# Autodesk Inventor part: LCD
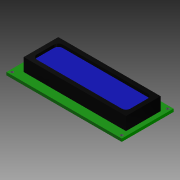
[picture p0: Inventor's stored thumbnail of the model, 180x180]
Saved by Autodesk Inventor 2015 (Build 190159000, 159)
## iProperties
Created: 2016-06
Part Number: LCD
Material: Genérico
Document SubType Name: Modeling
Designer: Diego
Density: 1 g/cm^3
Appearance: Valor por defecto
Author: Diego
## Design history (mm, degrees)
sketch "Boceto1"
  geometry: L1 (0, 0)-(80, 0); L2 (80, 0)-(80, 36); L3 (80, 36)-(0, 36); L4 (0, 36)-(0, 0)
  constraints: 8 end point, 2 parallel, 1 horizontal, 1 perpendicular
  dimensions: "d0" = 80 distance of L3.end L2.end; "d1" = 36 distance of L2.end L1.end
extrude "Extrusión1" new body sketch "Boceto1" distance "d2" = 2; taper "d3" = 0 deg
sketch "Boceto2"
  geometry: L1 (6, 30)-(77, 30); L2 (77, 30)-(77, 6); L3 (77, 6)-(6, 6); L4 (6, 6)-(6, 30); 1 further point
  constraints: 8 end point, 2 parallel, 1 horizontal, 1 perpendicular
  dimensions: "d10" = 71 distance of L2.end L3.end; "d11" = 24 distance of L1.end L2.end
extrude "Extrusión2" join sketch "Boceto2" distance "d12" = 9; taper "d13" = 0 deg
sketch "Boceto3"
  geometry: L1 (6, 30)-(6, 23); L2 (6, 30)-(6, 6) reference; L3 (6, 23)-(2, 23); L4 (6, 6)-(6, 13); L5 (6, 13)-(2, 13); L6 (2, 13)-(2, 23); L7 (6, 23)-(6, 13); 1 further point
  constraints: 12 end point, 2 parallel, 2 perpendicular, 2 point on line
  dimensions: "d14" = 7 distance of L1.start L1.end; "d15" = 4 distance of L1.end L3.end; "d16" = 7 distance of L2.end L4.end
extrude "Extrusión3" join sketch "Boceto3" distance "d17" = 5; taper "d18" = 0 deg
chamfer "Chaflán1" distance "d19" = 2; stored, may be unused: second distance "d20" = 2, angle "d21" = 45 deg
chamfer "Chaflán2" distance "d22" = 2; stored, may be unused: second distance "d23" = 2, angle "d24" = 45 deg
sketch "Boceto4"
  geometry: L1 (77, 30)-(6, 30) reference; L2 (6, 30)-(6, 6) reference; L3 (6, 6)-(77, 6) reference; L4 (77, 6)-(77, 30) reference; L5 (71, 9)-(12, 9); L6 (9, 12)-(9, 24); L7 (12, 27)-(71, 27); L8 (74, 24)-(74, 12); A1 r 3 centre (71, 12) between (71, 9) and (74, 12); A2 r 3 centre (71, 24) between (74, 24) and (71, 27); A3 r 3 centre (12, 24) between (12, 27) and (9, 24); A4 r 3 centre (12, 12) between (9, 12) and (12, 9); 1 further point
  constraints: 8 end point, 8 point on circle, 8 tangent, 4 centre point, 3 equal radius, 3 other
  dimensions: "d25" = 3 distance between parallel lines of L3 L5; "d26" = 3 radius of A1
extrude "Extrusión4" cut sketch "Boceto4" distance "d27" = 2; taper "d28" = 0 deg
sketch "Boceto5"
  geometry: L1 (0, 0)-(80, 0) reference; L2 (80, 0)-(80, 36) reference; L3 (80, 36)-(0, 36) reference; L4 (0, 36)-(0, 0) reference; L5 (6, 13)-(4, 13) reference; L6 (2, 15)-(4, 13) reference; L7 (2, 15)-(2, 21) reference; L8 (4, 23)-(2, 21) reference; L9 (4, 23)-(6, 23) reference; L10 (6, 23)-(6, 30) reference; L11 (6, 30)-(77, 30) reference; L12 (77, 30)-(77, 6) reference; L13 (77, 6)-(6, 6) reference; L14 (6, 6)-(6, 13) reference; L15 (78, 2)-(2, 2); L16 (2, 2)-(2, 34); L17 (2, 34)-(78, 34); L18 (78, 34)-(78, 2); 1 further point
  constraints: 8 end point, 3 other
  dimensions: "d29" = 2 distance between parallel lines of L1 L15
hole "Agujero1" sketch "Boceto5" at (78, 2), (78, 34), (2, 2), (2, 34) diameter "d30" = 2; stored, may be unused: countersink angle "d34" = 90 deg, drill point angle "d36" = 118 deg; dims "d31" = 6, "d32" = 4, "d33" = 2, "d35" = 8
sketch "Boceto6"
  geometry: L1 (-80, 0)-(-80, 36) reference; L2 (-80, 6)-(-36.384, 6); L3 (-77, 6)-(-6, 6) reference; L4 (-74.409, 6)-(-34.409, 6); L5 (-34.409, 6)-(-34.409, 8.5); L6 (-34.409, 8.5)-(-74.409, 8.5); L7 (-74.409, 8.5)-(-74.409, 6); 1 further point
  constraints: 10 end point, 3 point on line, 2 parallel, 1 horizontal, 1 perpendicular
  dimensions: "d37" = 40 distance of L6.end L5.end; "d38" = 2.5 distance of L5.end L4.end
extrude "Extrusión5" join sketch "Boceto6" distance "d39" = 2; taper "d40" = 0 deg
sketch "Boceto7" dims "d49" = 10
  geometry: L1 (-74.409, 6)-(-74.409, 8.5) reference; L2 (-34.409, 6)-(-34.409, 8.5) reference; L3 (-73.203, 7.25)-(-73.203, 6.5); L4 (-73.203, 6.5)-(-71.903, 6.5); L5 (-71.903, 6.5)-(-71.903, 7.8); L6 (-71.903, 7.8)-(-73.203, 7.8); L7 (-73.203, 7.8)-(-73.203, 6.5); L8 (-70.773, 7.25)-(-70.773, 6.5); L9 (-70.773, 6.5)-(-69.473, 6.5); L10 (-69.473, 6.5)-(-69.473, 7.8); L11 (-69.473, 7.8)-(-70.773, 7.8); L12 (-70.773, 7.8)-(-70.773, 6.5); L13 (-68.343, 7.25)-(-68.343, 6.5); L14 (-68.343, 6.5)-(-67.043, 6.5); L15 (-67.043, 6.5)-(-67.043, 7.8); L16 (-67.043, 7.8)-(-68.343, 7.8); L17 (-68.343, 7.8)-(-68.343, 6.5); L18 (-65.913, 7.25)-(-65.913, 6.5); L19 (-65.913, 6.5)-(-64.613, 6.5); L20 (-64.613, 6.5)-(-64.613, 7.8); L21 (-64.613, 7.8)-(-65.913, 7.8); L22 (-65.913, 7.8)-(-65.913, 6.5); L23 (-63.483, 7.25)-(-63.483, 6.5); L24 (-63.483, 6.5)-(-62.183, 6.5); L25 (-62.183, 6.5)-(-62.183, 7.8); L26 (-62.183, 7.8)-(-63.483, 7.8); L27 (-63.483, 7.8)-(-63.483, 6.5); L28 (-61.053, 7.25)-(-61.053, 6.5); L29 (-61.053, 6.5)-(-59.753, 6.5); L30 (-59.753, 6.5)-(-59.753, 7.8); L31 (-59.753, 7.8)-(-61.053, 7.8); L32 (-61.053, 7.8)-(-61.053, 6.5); L33 (-58.623, 7.25)-(-58.623, 6.5); L34 (-58.623, 6.5)-(-57.323, 6.5); L35 (-57.323, 6.5)-(-57.323, 7.8); L36 (-57.323, 7.8)-(-58.623, 7.8); L37 (-58.623, 7.8)-(-58.623, 6.5); L38 (-56.193, 7.25)-(-56.193, 6.5); L39 (-56.193, 6.5)-(-54.893, 6.5); L40 (-54.893, 6.5)-(-54.893, 7.8); L41 (-54.893, 7.8)-(-56.193, 7.8); L42 (-56.193, 7.8)-(-56.193, 6.5); L43 (-53.763, 7.25)-(-53.763, 6.5); L44 (-53.763, 6.5)-(-52.463, 6.5); L45 (-52.463, 6.5)-(-52.463, 7.8); L46 (-52.463, 7.8)-(-53.763, 7.8); L47 (-53.763, 7.8)-(-53.763, 6.5); L48 (-51.333, 7.25)-(-51.333, 6.5); L49 (-51.333, 6.5)-(-50.033, 6.5); L50 (-50.033, 6.5)-(-50.033, 7.8); L51 (-50.033, 7.8)-(-51.333, 7.8); L52 (-51.333, 7.8)-(-51.333, 6.5); L53 (-48.903, 7.25)-(-48.903, 6.5); L54 (-48.903, 6.5)-(-47.603, 6.5); L55 (-47.603, 6.5)-(-47.603, 7.8); L56 (-47.603, 7.8)-(-48.903, 7.8); L57 (-48.903, 7.8)-(-48.903, 6.5); L58 (-46.473, 7.25)-(-46.473, 6.5); L59 (-46.473, 6.5)-(-45.173, 6.5); L60 (-45.173, 6.5)-(-45.173, 7.8); L61 (-45.173, 7.8)-(-46.473, 7.8); L62 (-46.473, 7.8)-(-46.473, 6.5); L63 (-44.043, 7.25)-(-44.043, 6.5); L64 (-44.043, 6.5)-(-42.743, 6.5)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; 1 further point
  constraints: 160 end point, 2 horizontal, 2 parallel, 1 collinear, 1 perpendicular, 1 vertical, 149 other
  dimensions: "d41" = 0.75 distance of L3.start L3.end; "d42" = 1.3 distance of L6.end L5.end; "d43" = 1.3 distance of L5.end L4.end; "d46" = 2.43 distance of L3.start L8.start
extrude "Extrusión6" join sketch "Boceto7" distance "d51" = 4; taper "d52" = 0 deg
sketch "Boceto8" dims "d59" = 10
  geometry: L1 (-73.203, 6.5)-(-71.903, 6.5) reference; L2 (-71.903, 6.5)-(-71.903, 7.8) reference; L3 (-71.903, 7.8)-(-73.203, 7.8) reference; L4 (-73.203, 7.8)-(-73.203, 6.5) reference; L5 (-72.803, 7.4)-(-72.303, 7.4); L6 (-72.303, 7.4)-(-72.303, 6.9); L7 (-72.303, 6.9)-(-72.803, 6.9); L8 (-72.803, 6.9)-(-72.803, 7.4); L9 (-70.373, 6.9)-(-70.373, 7.4); L10 (-70.373, 7.4)-(-69.873, 7.4); L11 (-69.873, 6.9)-(-70.373, 6.9); L12 (-69.873, 7.4)-(-69.873, 6.9); L13 (-67.943, 6.9)-(-67.943, 7.4); L14 (-67.943, 7.4)-(-67.443, 7.4); L15 (-67.443, 6.9)-(-67.943, 6.9); L16 (-67.443, 7.4)-(-67.443, 6.9); L17 (-65.513, 6.9)-(-65.513, 7.4); L18 (-65.513, 7.4)-(-65.013, 7.4); L19 (-65.013, 6.9)-(-65.513, 6.9); L20 (-65.013, 7.4)-(-65.013, 6.9); L21 (-63.083, 6.9)-(-63.083, 7.4); L22 (-63.083, 7.4)-(-62.583, 7.4); L23 (-62.583, 6.9)-(-63.083, 6.9); L24 (-62.583, 7.4)-(-62.583, 6.9); L25 (-60.653, 6.9)-(-60.653, 7.4); L26 (-60.653, 7.4)-(-60.153, 7.4); L27 (-60.153, 6.9)-(-60.653, 6.9); L28 (-60.153, 7.4)-(-60.153, 6.9); L29 (-58.223, 6.9)-(-58.223, 7.4); L30 (-58.223, 7.4)-(-57.723, 7.4); L31 (-57.723, 6.9)-(-58.223, 6.9); L32 (-57.723, 7.4)-(-57.723, 6.9); L33 (-55.793, 6.9)-(-55.793, 7.4); L34 (-55.793, 7.4)-(-55.293, 7.4); L35 (-55.293, 6.9)-(-55.793, 6.9); L36 (-55.293, 7.4)-(-55.293, 6.9); L37 (-53.363, 6.9)-(-53.363, 7.4); L38 (-53.363, 7.4)-(-52.863, 7.4); L39 (-52.863, 6.9)-(-53.363, 6.9); L40 (-52.863, 7.4)-(-52.863, 6.9); L41 (-50.933, 6.9)-(-50.933, 7.4); L42 (-50.933, 7.4)-(-50.433, 7.4); L43 (-50.433, 6.9)-(-50.933, 6.9); L44 (-50.433, 7.4)-(-50.433, 6.9); L45 (-48.503, 6.9)-(-48.503, 7.4); L46 (-48.503, 7.4)-(-48.003, 7.4); L47 (-48.003, 6.9)-(-48.503, 6.9); L48 (-48.003, 7.4)-(-48.003, 6.9); L49 (-46.073, 6.9)-(-46.073, 7.4); L50 (-46.073, 7.4)-(-45.573, 7.4); L51 (-45.573, 6.9)-(-46.073, 6.9); L52 (-45.573, 7.4)-(-45.573, 6.9); L53 (-43.643, 6.9)-(-43.643, 7.4); L54 (-43.643, 7.4)-(-43.143, 7.4); L55 (-43.143, 6.9)-(-43.643, 6.9); L56 (-43.143, 7.4)-(-43.143, 6.9); L57 (-41.213, 6.9)-(-41.213, 7.4); L58 (-41.213, 7.4)-(-40.713, 7.4); L59 (-40.713, 6.9)-(-41.213, 6.9); L60 (-40.713, 7.4)-(-40.713, 6.9); L61 (-38.783, 6.9)-(-38.783, 7.4); L62 (-38.783, 7.4)-(-38.283, 7.4); L63 (-38.283, 6.9)-(-38.783, 6.9); L64 (-38.283, 7.4)-(-38.283, 6.9)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; 1 further point
  constraints: 128 end point, 1 collinear, 1 horizontal, 122 other
  dimensions: "d53" = 0.4 distance between parallel lines of L3 L5; "d56" = 2.43 distance of L7.end L9.start
extrude "Extrusión7" join sketch "Boceto8" distance "d61" = 0.6; taper "d62" = 0 deg
feature "Solevación1" dims "d63" = 0, "d64" = 90 deg, "d65" = 0, "d66" = 90 deg
  node "Aristas1"
  node "Aristas2"
feature "Solevación2" dims "d67" = 0, "d68" = 90 deg, "d69" = 0, "d70" = 90 deg
  node "Aristas3"
  node "Aristas4"
feature "Solevación3" dims "d71" = 0, "d72" = 90 deg, "d73" = 0, "d74" = 90 deg
  node "Aristas5"
  node "Aristas6"
feature "Solevación4" dims "d75" = 0, "d76" = 90 deg, "d77" = 0, "d78" = 90 deg
  node "Aristas7"
  node "Aristas8"
feature "Solevación5" dims "d79" = 0, "d80" = 90 deg, "d81" = 0, "d82" = 90 deg
  node "Aristas9"
  node "Aristas10"
feature "Solevación6" dims "d83" = 0, "d84" = 90 deg, "d85" = 0, "d86" = 90 deg
  node "Aristas11"
  node "Aristas12"
feature "Solevación7" dims "d87" = 0, "d88" = 90 deg, "d89" = 0, "d90" = 90 deg
  node "Aristas13"
  node "Aristas14"
feature "Solevación8" dims "d91" = 0, "d92" = 90 deg, "d93" = 0, "d94" = 90 deg
  node "Aristas15"
  node "Aristas16"
feature "Solevación9" dims "d95" = 0, "d96" = 90 deg, "d97" = 0, "d98" = 90 deg
  node "Aristas17"
  node "Aristas18"
feature "Solevación10" dims "d99" = 0, "d100" = 90 deg, "d101" = 0, "d102" = 90 deg
  node "Aristas19"
  node "Aristas20"
feature "Solevación11" dims "d103" = 0, "d104" = 90 deg, "d105" = 0, "d106" = 90 deg
  node "Aristas21"
  node "Aristas22"
feature "Solevación12" dims "d107" = 0, "d108" = 90 deg, "d109" = 0, "d110" = 90 deg
  node "Aristas23"
  node "Aristas24"
feature "Solevación13" dims "d111" = 0, "d112" = 90 deg, "d113" = 0, "d114" = 90 deg
  node "Aristas25"
  node "Aristas26"
feature "Solevación14" dims "d115" = 0, "d116" = 90 deg, "d117" = 0, "d118" = 90 deg
  node "Aristas27"
  node "Aristas28"
feature "Solevación15" dims "d119" = 0, "d120" = 90 deg, "d121" = 0, "d122" = 90 deg
  node "Aristas29"
  node "Aristas30"
feature "Solevación16" dims "d123" = 0, "d124" = 90 deg, "d125" = 0, "d126" = 90 deg
  node "Aristas31"
  node "Aristas32"
sketch "Boceto9"
  geometry: L1 (0, 36)-(0, 0) reference; L2 (0, 18)-(-79.952, 18); L3 (-12, 27)-(-71, 27) reference; C1 r 9 at (-13.582, 18); C2 r 5.773 at (-62.846, 18)
  constraints: 2 centre point, 2 end point, 2 point on line, 1 horizontal, 1 midpoint, 1 tangent
extrude "Extrusión8" join sketch "Boceto9" distance "d127" = 0.6; taper "d128" = 0 deg
fillet "Empalme1" dims "d129" = 0.6
fillet "Empalme2" dims "d130" = 0.6
node "Sólido1"
node "Contorno proyectado1"
node "Contorno proyectado2"
node "Contorno proyectado3"
